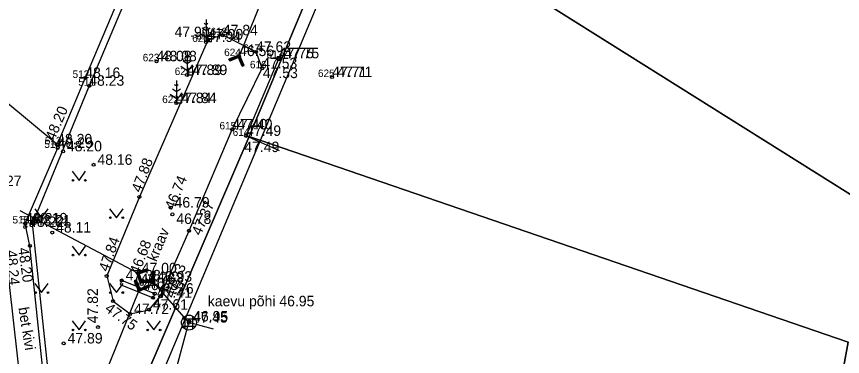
# Model space of a CAD drawing. Extents: x 640876 to 641418, y 6455595 to 6456085.
# Drawn here: x 641197.9 to 641253.1, y 6455921.6 to 6455944.3 of the extents above; entities that cross this region are included whole.
import ezdxf

# ---------------------------------------------------------------- set-up
doc = ezdxf.new("R2010")
doc.units = 0
for name, color, linetype in [('ABIJOONIS', 7, 'Continuous'), ('AED', 7, 'Continuous'), ('DKAEV', 7, 'Continuous'), ('DTRASS', 7, 'Continuous'), ('HALJASTUS', 7, 'Continuous'), ('KORGUS', 7, 'Continuous'), ('MOOTKORG', 7, 'Continuous'), ('MOOTKORG_MUU', 7, 'Continuous'), ('MOOTMPUNKT', 7, 'Continuous'), ('MOOTNR', 7, 'Continuous'), ('MOOTPIIR', 7, 'Continuous'), ('PIIR', 7, 'Continuous'), ('PUU', 7, 'Continuous'), ('SKTRASS', 7, 'Continuous'), ('TEE', 7, 'Continuous'), ('TRUUP', 7, 'Continuous'), ('VEEKOGU', 7, 'Continuous')]:
    doc.layers.add(name, color=color, linetype=linetype)

msp = doc.modelspace()

# ---------------------------------------------------------------- linework, layer by layer
at = {"layer": 'AED'}
for p, q in [((641215.287, 6455941.607), (641215.287, 6455941.357)), ((641215.287, 6455941.607), (641215.537, 6455941.607)), ((641215.537, 6455941.607), (641215.537, 6455941.357)), ((641215.287, 6455941.357), (641215.537, 6455941.357))]:
    msp.add_line(p, q, dxfattribs=at)
for points in [[(641160.606, 6455994.253), (641178.047, 6455995.168), (641191.652, 6455995.856), (641207.752, 6455996.687), (641222.341, 6455997.449), (641221.765, 6455994.718), (641219.959, 6455985.906), (641217.708, 6455975.561), (641214.2, 6455967.017), (641207.311, 6455950.541), (641202.719, 6455939.647), (641198.916, 6455930.446)], [(641215.412, 6455941.482), (641213.217, 6455936.294), (641215.427, 6455935.323)], [(641212.909, 6455897.356), (641213.691, 6455898.428), (641207.414, 6455903.573), (641201.239, 6455908.657), (641199.959, 6455920.79), (641198.916, 6455930.446)]]:
    msp.add_lwpolyline(points, dxfattribs=at)
at = {"layer": 'DKAEV'}
for p, q in [((641208.955, 6455924.063), (641209.821, 6455924.063)), ((641209.138, 6455923.38), (641209.138, 6455924.246)), ((641209.638, 6455924.246), (641209.638, 6455923.38)), ((641209.821, 6455923.563), (641208.955, 6455923.563))]:
    msp.add_line(p, q, dxfattribs=at)
msp.add_circle((641209.388, 6455923.813), 0.5, dxfattribs=at)
at = {"layer": 'DTRASS'}
for p, q in [((641206.935, 6455926.624), (641206.978, 6455927.258)), ((641206.964, 6455927.057), (641207.101, 6455926.976)), ((641206.966, 6455927.085), (641207.103, 6455927.004)), ((641206.968, 6455927.113), (641207.105, 6455927.032)), ((641206.97, 6455927.141), (641207.107, 6455927.06)), ((641206.972, 6455927.169), (641207.109, 6455927.088)), ((641206.974, 6455927.197), (641207.111, 6455927.116)), ((641206.976, 6455927.225), (641207.113, 6455927.144)), ((641206.978, 6455927.258), (641207.12, 6455927.249)), ((641206.978, 6455927.253), (641207.115, 6455927.172)), ((641207.001, 6455926.548), (641207.049, 6455927.253)), ((641207.022, 6455927.255), (641207.117, 6455927.199)), ((641207.067, 6455926.472), (641207.12, 6455927.249)), ((641207.078, 6455927.252), (641207.119, 6455927.227)), ((641205.851, 6455926.666), (641205.719, 6455926.611)), ((641205.719, 6455926.611), (641206.022, 6455925.894)), ((641205.746, 6455926.622), (641205.742, 6455926.557)), ((641205.772, 6455926.633), (641205.764, 6455926.506)), ((641205.798, 6455926.644), (641205.785, 6455926.455)), ((641205.785, 6455926.638), (641206.06, 6455925.987)), ((641205.824, 6455926.655), (641205.807, 6455926.403)), ((641205.85, 6455926.666), (641205.828, 6455926.352)), ((641205.871, 6455926.617), (641205.85, 6455926.301)), ((641205.851, 6455926.666), (641206.098, 6455926.08)), ((641205.893, 6455926.566), (641205.872, 6455926.25)), ((641205.915, 6455926.514), (641205.893, 6455926.199)), ((641206.3, 6455926.667), (641206.291, 6455926.525)), ((641206.291, 6455926.525), (641207.067, 6455926.472)), ((641206.293, 6455926.554), (641206.349, 6455926.521)), ((641206.295, 6455926.582), (641206.404, 6455926.517)), ((641206.296, 6455926.61), (641206.46, 6455926.513)), ((641206.296, 6455926.596), (641207.001, 6455926.548)), ((641206.298, 6455926.638), (641206.515, 6455926.51)), ((641206.3, 6455926.667), (641206.935, 6455926.624)), ((641206.3, 6455926.666), (641206.571, 6455926.506)), ((641206.354, 6455926.663), (641206.626, 6455926.502)), ((641206.409, 6455926.66), (641206.681, 6455926.498)), ((641206.465, 6455926.656), (641206.737, 6455926.495)), ((641206.52, 6455926.652), (641206.792, 6455926.491)), ((641206.575, 6455926.648), (641206.848, 6455926.487)), ((641206.631, 6455926.644), (641206.903, 6455926.483)), ((641206.686, 6455926.641), (641206.959, 6455926.48)), ((641206.742, 6455926.637), (641207.014, 6455926.476)), ((641206.797, 6455926.633), (641207.067, 6455926.473)), ((641206.853, 6455926.629), (641207.069, 6455926.501)), ((641206.908, 6455926.626), (641207.071, 6455926.529)), ((641206.936, 6455926.638), (641207.073, 6455926.557)), ((641206.938, 6455926.666), (641207.075, 6455926.585)), ((641206.94, 6455926.694), (641207.077, 6455926.613)), ((641206.941, 6455926.722), (641207.079, 6455926.641)), ((641206.943, 6455926.75), (641207.081, 6455926.669)), ((641206.945, 6455926.778), (641207.082, 6455926.697)), ((641206.947, 6455926.806), (641207.084, 6455926.725)), ((641206.949, 6455926.834), (641207.086, 6455926.753)), ((641206.951, 6455926.862), (641207.088, 6455926.781)), ((641206.953, 6455926.89), (641207.09, 6455926.808)), ((641206.955, 6455926.918), (641207.092, 6455926.836)), ((641206.957, 6455926.946), (641207.094, 6455926.864)), ((641206.959, 6455926.973), (641207.096, 6455926.892)), ((641206.96, 6455927.001), (641207.098, 6455926.92)), ((641206.962, 6455927.029), (641207.1, 6455926.948)), ((641209.388, 6455923.813), (641207.001, 6455926.548)), ((641198.97, 6455908.534), (641206.06, 6455925.987)), ((641205.936, 6455926.463), (641205.915, 6455926.148)), ((641205.958, 6455926.412), (641205.937, 6455926.096)), ((641205.979, 6455926.361), (641205.958, 6455926.045)), ((641206.001, 6455926.31), (641205.98, 6455925.994)), ((641206.023, 6455926.259), (641206.001, 6455925.943)), ((641206.022, 6455925.894), (641206.739, 6455926.196)), ((641206.044, 6455926.207), (641206.023, 6455925.894)), ((641206.066, 6455926.156), (641206.049, 6455925.905)), ((641206.06, 6455925.987), (641206.711, 6455926.262)), ((641206.087, 6455926.105), (641206.075, 6455925.916)), ((641206.098, 6455926.08), (641206.684, 6455926.328)), ((641206.111, 6455926.086), (641206.101, 6455925.927)), ((641206.137, 6455926.097), (641206.126, 6455925.938)), ((641206.163, 6455926.108), (641206.152, 6455925.949)), ((641206.189, 6455926.119), (641206.178, 6455925.96)), ((641206.214, 6455926.129), (641206.204, 6455925.97)), ((641206.24, 6455926.14), (641206.229, 6455925.981)), ((641206.266, 6455926.151), (641206.255, 6455925.992)), ((641206.292, 6455926.162), (641206.281, 6455926.003)), ((641206.318, 6455926.173), (641206.307, 6455926.014)), ((641206.343, 6455926.184), (641206.333, 6455926.025)), ((641206.369, 6455926.195), (641206.358, 6455926.036)), ((641206.395, 6455926.206), (641206.384, 6455926.047)), ((641206.421, 6455926.217), (641206.41, 6455926.058)), ((641206.446, 6455926.227), (641206.436, 6455926.068)), ((641206.472, 6455926.238), (641206.462, 6455926.079)), ((641206.498, 6455926.249), (641206.487, 6455926.09)), ((641206.524, 6455926.26), (641206.513, 6455926.101)), ((641206.55, 6455926.271), (641206.539, 6455926.112)), ((641206.575, 6455926.282), (641206.565, 6455926.123)), ((641206.601, 6455926.293), (641206.591, 6455926.134)), ((641206.627, 6455926.304), (641206.616, 6455926.145)), ((641206.653, 6455926.315), (641206.642, 6455926.156)), ((641206.679, 6455926.325), (641206.668, 6455926.166)), ((641206.684, 6455926.328), (641206.739, 6455926.196)), ((641206.701, 6455926.287), (641206.694, 6455926.177)), ((641206.723, 6455926.235), (641206.719, 6455926.188)), ((641206.913, 6455914.714), (641209.388, 6455923.813)), ((641211.031, 6455923.377), (641209.388, 6455923.813))]:
    msp.add_line(p, q, dxfattribs=at)
at = {"layer": 'HALJASTUS'}
for p, q in [((641201.571, 6455933.93), (641202.035, 6455933.324)), ((641202.035, 6455933.324), (641202.48, 6455933.93)), ((641199.071, 6455931.43), (641199.535, 6455930.824)), ((641199.535, 6455930.824), (641199.98, 6455931.43)), ((641204.071, 6455931.43), (641204.535, 6455930.824)), ((641204.535, 6455930.824), (641204.98, 6455931.43)), ((641201.571, 6455928.93), (641202.035, 6455928.324)), ((641202.035, 6455928.324), (641202.48, 6455928.93)), ((641199.071, 6455926.43), (641199.535, 6455925.824)), ((641199.535, 6455925.824), (641199.98, 6455926.43)), ((641204.071, 6455926.43), (641204.535, 6455925.824)), ((641204.535, 6455925.824), (641204.98, 6455926.43)), ((641201.571, 6455923.93), (641202.035, 6455923.324)), ((641202.035, 6455923.324), (641202.48, 6455923.93)), ((641206.571, 6455923.93), (641207.035, 6455923.324)), ((641207.035, 6455923.324), (641207.48, 6455923.93))]:
    msp.add_line(p, q, dxfattribs=at)
for centre in [(641201.634, 6455933.324), (641202.463, 6455933.324), (641199.134, 6455930.824), (641199.963, 6455930.824), (641204.134, 6455930.824), (641204.963, 6455930.824), (641201.634, 6455928.324), (641202.463, 6455928.324), (641199.134, 6455925.824), (641199.963, 6455925.824), (641204.134, 6455925.824), (641204.963, 6455925.824), (641201.634, 6455923.324), (641202.463, 6455923.324), (641206.634, 6455923.324), (641207.463, 6455923.324)]:
    msp.add_circle(centre, 0.055, dxfattribs=at)
at = {"layer": 'KORGUS'}
for centre in [(641210.68, 6455942.742), (641215.412, 6455941.482), (641207.223, 6455941.282), (641214.296, 6455940.813), (641209.264, 6455940.362), (641218.974, 6455940.229), (641208.551, 6455938.487), (641212.285, 6455936.73), (641213.217, 6455936.294), (641200.572, 6455935.729), (641203.009, 6455934.361), (641206.075, 6455932.221), (641208.286, 6455931.048), (641200.244, 6455929.836), (641209.398, 6455929.953), (641198.745, 6455928.944), (641203.888, 6455926.932), (641206.231, 6455926.396), (641207.472, 6455925.561), (641204.318, 6455925.253), (641203.299, 6455923.51), (641201.009, 6455922.421)]:
    msp.add_circle(centre, 0.1, dxfattribs=at)
at = {"layer": 'MOOTMPUNKT'}
for centre in [(641211.663, 6455943.019), (641210.535, 6455942.572), (641210.68, 6455942.742), (641213.882, 6455941.911), (641212.747, 6455941.628), (641215.412, 6455941.482), (641207.223, 6455941.282), (641214.296, 6455940.813), (641209.264, 6455940.362), (641218.974, 6455940.229), (641202.453, 6455940.169), (641202.719, 6455939.647), (641208.551, 6455938.487), (641212.285, 6455936.73), (641213.217, 6455936.294), (641200.572, 6455935.729), (641200.615, 6455935.492), (641200.968, 6455935.261), (641208.171, 6455931.503), (641198.434, 6455930.44), (641198.87, 6455930.305), (641198.916, 6455930.446), (641198.436, 6455930.206), (641205.972, 6455927.113), (641204.896, 6455926.636), (641205.895, 6455926.395), (641207.001, 6455926.548), (641206.06, 6455925.987), (641206.461, 6455926.112), (641206.986, 6455925.475), (641207.1, 6455925.748), (641205.458, 6455924.391), (641206.72, 6455924.676), (641209.388, 6455923.813), (641209.414, 6455923.892)]:
    msp.add_circle(centre, 0.1, dxfattribs=at)
at = {"layer": 'MOOTPIIR'}
msp.add_lwpolyline([(641060.916, 6455895.936), (641100.061, 6455950.482), (641099.586, 6455952.159), (641069.132, 6455984.035), (641066.132, 6455988.623), (641076.463, 6456005.049), (641230.642, 6456010.048), (641237.36, 6455995.24), (641237.24, 6455992.81), (641236.258, 6455990.888), (641229.041, 6455971.315), (641203.026, 6455909.57), (641225.257, 6455906.847), (641239.512, 6455898.491), (641200.195, 6455851.697), (641192.016, 6455859.099), (641169.785, 6455829.138), (641192.025, 6455807.568), (641252.96, 6455758.075), (641231.388, 6455736.74), (641191.474, 6455775.975), (641152.419, 6455787.914), (641136.351, 6455788.307), (641049.066, 6455856.043)], dxfattribs=at)
at = {"layer": 'PIIR'}
for points in [[(641222.58, 6455998.61), (641237.36, 6455995.24), (641235.34, 6455991.29), (641228.11, 6455971.68), (641220.5, 6455953.19), (641213.41, 6455936.25), (641201.58, 6455908.74), (641224.93, 6455905.88), (641191.87, 6455860.58), (641157.02, 6455885.66), (641160.91, 6455891.99), (641102.26, 6455951.82), (641074.95, 6455979.64), (641084.84, 6455991.92)], [(641280.77, 6455915.37), (641220.5, 6455953.19), (641228.11, 6455971.68), (641291.33, 6455932.26)], [(641270.69, 6455899.15), (641249.88, 6455902.84), (641253.51, 6455922.51), (641213.41, 6455936.25), (641220.5, 6455953.19), (641280.77, 6455915.37)], [(641201.58, 6455908.74), (641213.41, 6455936.25), (641253.51, 6455922.51), (641249.88, 6455902.84)]]:
    msp.add_lwpolyline(points, close=True, dxfattribs=at)
at = {"layer": 'PUU'}
for p, q in [((641210.535, 6455943.722), (641210.411, 6455943.805)), ((641210.535, 6455944.072), (641210.535, 6455942.572)), ((641210.66, 6455943.805), (641210.535, 6455943.722)), ((641210.111, 6455943.161), (641210.535, 6455942.878)), ((641210.535, 6455943.322), (641210.269, 6455943.5)), ((641210.802, 6455943.5), (641210.535, 6455943.322)), ((641210.535, 6455942.878), (641210.96, 6455943.161)), ((641210.895, 6455942.572), (641210.535, 6455942.572)), ((641209.264, 6455941.512), (641209.139, 6455941.595)), ((641209.264, 6455941.862), (641209.264, 6455940.362)), ((641209.388, 6455941.595), (641209.264, 6455941.512)), ((641208.839, 6455940.951), (641209.264, 6455940.668)), ((641209.264, 6455941.112), (641208.997, 6455941.289)), ((641209.53, 6455941.289), (641209.264, 6455941.112)), ((641209.264, 6455940.668), (641209.688, 6455940.951)), ((641209.624, 6455940.362), (641209.264, 6455940.362)), ((641208.551, 6455939.987), (641208.551, 6455938.487)), ((641208.551, 6455939.237), (641208.284, 6455939.414)), ((641208.551, 6455939.637), (641208.426, 6455939.719)), ((641208.675, 6455939.719), (641208.551, 6455939.637)), ((641208.817, 6455939.414), (641208.551, 6455939.237)), ((641208.127, 6455939.076), (641208.551, 6455938.793)), ((641208.551, 6455938.793), (641208.975, 6455939.076)), ((641208.911, 6455938.487), (641208.551, 6455938.487))]:
    msp.add_line(p, q, dxfattribs=at)
at = {"layer": 'SKTRASS'}
for p, q in [((641205.972, 6455927.113), (641198.106, 6455931.289)), ((641206.622, 6455927.401), (641205.882, 6455927.158)), ((641205.882, 6455927.158), (641206.125, 6455926.419)), ((641206.193, 6455927.111), (641205.883, 6455927.157)), ((641206.14, 6455927.093), (641205.891, 6455927.131)), ((641206.087, 6455927.076), (641205.9, 6455927.104)), ((641206.066, 6455927.054), (641205.909, 6455927.078)), ((641206.075, 6455927.027), (641205.917, 6455927.051)), ((641206.246, 6455927.128), (641205.933, 6455927.175)), ((641206.644, 6455927.334), (641205.972, 6455927.113)), ((641205.972, 6455927.113), (641206.193, 6455926.441)), ((641206.298, 6455927.145), (641205.986, 6455927.192)), ((641206.351, 6455927.163), (641206.038, 6455927.21)), ((641206.666, 6455927.266), (641206.062, 6455927.068)), ((641206.062, 6455927.068), (641206.26, 6455926.463)), ((641206.404, 6455927.18), (641206.091, 6455927.227)), ((641206.457, 6455927.197), (641206.144, 6455927.244)), ((641206.51, 6455927.215), (641206.197, 6455927.262)), ((641206.562, 6455927.232), (641206.249, 6455927.279)), ((641206.615, 6455927.249), (641206.302, 6455927.296)), ((641206.666, 6455927.267), (641206.355, 6455927.314)), ((641206.657, 6455927.294), (641206.408, 6455927.331)), ((641206.648, 6455927.32), (641206.461, 6455927.348)), ((641206.639, 6455927.347), (641206.513, 6455927.366)), ((641206.631, 6455927.373), (641206.566, 6455927.383)), ((641206.666, 6455927.266), (641206.622, 6455927.401)), ((641206.084, 6455927.001), (641205.926, 6455927.024)), ((641206.093, 6455926.974), (641205.935, 6455926.998)), ((641206.101, 6455926.947), (641205.944, 6455926.971)), ((641206.11, 6455926.921), (641205.952, 6455926.945)), ((641206.119, 6455926.894), (641205.961, 6455926.918)), ((641206.128, 6455926.868), (641205.97, 6455926.891)), ((641206.136, 6455926.841), (641205.979, 6455926.865)), ((641206.145, 6455926.814), (641205.987, 6455926.838)), ((641206.154, 6455926.788), (641205.996, 6455926.812)), ((641206.162, 6455926.761), (641206.005, 6455926.785)), ((641206.171, 6455926.735), (641206.014, 6455926.758)), ((641206.18, 6455926.708), (641206.022, 6455926.732)), ((641206.189, 6455926.681), (641206.031, 6455926.705)), ((641206.197, 6455926.655), (641206.04, 6455926.679)), ((641206.206, 6455926.628), (641206.049, 6455926.652)), ((641206.215, 6455926.602), (641206.057, 6455926.625)), ((641206.224, 6455926.575), (641206.066, 6455926.599)), ((641206.232, 6455926.549), (641206.075, 6455926.572)), ((641206.241, 6455926.522), (641206.084, 6455926.546)), ((641206.25, 6455926.495), (641206.092, 6455926.519)), ((641206.259, 6455926.469), (641206.101, 6455926.492)), ((641206.218, 6455926.45), (641206.11, 6455926.466)), ((641206.165, 6455926.432), (641206.118, 6455926.439)), ((641206.26, 6455926.463), (641206.125, 6455926.419))]:
    msp.add_line(p, q, dxfattribs=at)
at = {"layer": 'TEE'}
msp.add_line((641198.434, 6455930.44), (641200.615, 6455935.492), dxfattribs=at)
for points in [[(641219.562, 6455985.852), (641216.822, 6455976.794), (641214.309, 6455968.346), (641210.175, 6455958.541), (641206.979, 6455950.86), (641202.453, 6455940.169), (641200.572, 6455935.729), (641195.267, 6455940.101), (641183.381, 6455949.957), (641172.174, 6455959.233), (641160.995, 6455968.496)], [(641195.845, 6455932.936), (641197.091, 6455928.74), (641198.157, 6455919.205), (641198.959, 6455910.955), (641196.671, 6455908.21)], [(641227.727, 6455889.418), (641222.234, 6455890.597), (641218.433, 6455893.816), (641212.015, 6455899.131), (641206.417, 6455903.827), (641200.844, 6455908.419), (641200.675, 6455911.228), (641199.697, 6455919.825), (641198.745, 6455928.944), (641198.434, 6455930.44)]]:
    msp.add_lwpolyline(points, dxfattribs=at)
at = {"layer": 'TRUUP'}
for p, q in [((641212.784, 6455941.722), (641212.068, 6455941.417)), ((641212.124, 6455941.286), (641212.068, 6455941.417)), ((641212.085, 6455941.378), (641212.088, 6455941.425)), ((641212.747, 6455941.628), (641212.096, 6455941.351)), ((641212.107, 6455941.327), (641212.114, 6455941.436)), ((641212.709, 6455941.535), (641212.124, 6455941.286)), ((641212.129, 6455941.288), (641212.139, 6455941.447)), ((641212.155, 6455941.299), (641212.165, 6455941.458)), ((641212.181, 6455941.31), (641212.191, 6455941.469)), ((641212.207, 6455941.321), (641212.217, 6455941.48)), ((641212.232, 6455941.332), (641212.242, 6455941.491)), ((641212.258, 6455941.343), (641212.268, 6455941.502)), ((641212.284, 6455941.354), (641212.294, 6455941.513)), ((641212.31, 6455941.365), (641212.32, 6455941.524)), ((641212.335, 6455941.376), (641212.345, 6455941.535)), ((641212.361, 6455941.387), (641212.371, 6455941.546)), ((641212.387, 6455941.398), (641212.397, 6455941.557)), ((641212.413, 6455941.409), (641212.423, 6455941.568)), ((641212.438, 6455941.42), (641212.448, 6455941.579)), ((641212.464, 6455941.431), (641212.474, 6455941.59)), ((641212.49, 6455941.442), (641212.5, 6455941.601)), ((641212.516, 6455941.453), (641212.526, 6455941.612)), ((641212.541, 6455941.464), (641212.551, 6455941.623)), ((641212.567, 6455941.475), (641212.577, 6455941.634)), ((641212.593, 6455941.486), (641212.603, 6455941.645)), ((641212.619, 6455941.496), (641212.629, 6455941.656)), ((641212.644, 6455941.507), (641212.655, 6455941.667)), ((641212.67, 6455941.518), (641212.68, 6455941.678)), ((641212.696, 6455941.529), (641212.706, 6455941.689)), ((641212.958, 6455940.95), (641212.709, 6455941.535)), ((641212.72, 6455941.51), (641212.732, 6455941.699)), ((641212.741, 6455941.459), (641212.758, 6455941.71)), ((641213.024, 6455940.978), (641212.747, 6455941.628)), ((641212.763, 6455941.408), (641212.783, 6455941.721)), ((641213.089, 6455941.006), (641212.784, 6455941.722)), ((641212.785, 6455941.357), (641212.805, 6455941.673)), ((641212.807, 6455941.306), (641212.827, 6455941.622)), ((641212.829, 6455941.255), (641212.849, 6455941.571)), ((641212.85, 6455941.204), (641212.871, 6455941.519)), ((641212.872, 6455941.153), (641212.892, 6455941.468)), ((641212.894, 6455941.102), (641212.914, 6455941.417)), ((641212.916, 6455941.05), (641212.936, 6455941.366)), ((641212.938, 6455940.999), (641212.958, 6455941.315)), ((641212.958, 6455940.95), (641213.089, 6455941.006)), ((641212.959, 6455940.95), (641212.979, 6455941.264)), ((641212.985, 6455940.961), (641213.001, 6455941.213)), ((641213.011, 6455940.972), (641213.023, 6455941.162)), ((641213.037, 6455940.983), (641213.045, 6455941.111)), ((641213.062, 6455940.994), (641213.067, 6455941.06))]:
    msp.add_line(p, q, dxfattribs=at)
for points in [[(641215.125, 6455947.499), (641212.747, 6455941.628)], [(641204.896, 6455926.636), (641204.782, 6455926.363), (641206.986, 6455925.475), (641207.1, 6455925.748), (641204.896, 6455926.636)]]:
    msp.add_lwpolyline(points, dxfattribs=at)
at = {"layer": 'VEEKOGU'}
for points in [[(641209.77, 6455930.802), (641212.285, 6455936.73), (641214.296, 6455940.813), (641213.882, 6455941.911), (641211.663, 6455943.019), (641210.68, 6455942.742), (641206.075, 6455932.221)], [(641206.075, 6455932.221), (641203.888, 6455926.932), (641204.318, 6455925.253), (641205.458, 6455924.391), (641206.72, 6455924.676), (641207.472, 6455925.561), (641209.398, 6455929.953), (641209.77, 6455930.802)]]:
    msp.add_lwpolyline(points, dxfattribs=at)

# ---------------------------------------------------------------- texts
at = {"layer": 'ABIJOONIS'}
msp.add_text('kaevu põhi 46.95', height=0.7, dxfattribs=at).set_placement((641210.652, 6455924.904))
at = {"layer": 'DKAEV'}
msp.add_text('kaevu põhi 46.95', height=0.7, dxfattribs=at).set_placement((641210.652, 6455924.904))
at = {"layer": 'KORGUS'}
for s, p in [('47.90', (641208.429, 6455942.897)), ('48.08', (641207.573, 6455941.282)), ('47.75', (641215.762, 6455941.482)), ('47.89', (641209.614, 6455940.362)), ('47.53', (641214.335, 6455940.156)), ('47.71', (641219.324, 6455940.229)), ('47.84', (641208.901, 6455938.487)), ('47.40', (641212.635, 6455936.73)), ('47.49', (641213.095, 6455935.212)), (' 48.16', (641203.009, 6455934.361)), (' 48.11', (641200.244, 6455929.836)), (' 47.89', (641201.009, 6455922.421))]:
    msp.add_text(s, height=0.7, dxfattribs=at).set_placement(p)
for s, rotation, p in [('48.20', 66.6899, (641200.388, 6455935.937)), (' 47.88', 69.1723, (641206.075, 6455932.221)), (' 46.74', 67.3926, (641208.286, 6455931.048)), (' 47.37', 66.6924, (641210.078, 6455929.35)), (' 47.84', 70.0885, (641203.888, 6455926.932)), (' 46.68', 68.5544, (641205.947, 6455926.737)), (' 48.20', 278.0679, (641197.922, 6455929.042)), (' 48.24', 274.847, (641197.151, 6455928.887)), (' 47.33', 69.2743, (641208.287, 6455925.163)), (' 47.82', 90, (641203.299, 6455923.51)), (' 47.75', 323.9814, (641203.503, 6455924.779))]:
    msp.add_text(s, height=0.7, rotation=rotation, dxfattribs=at).set_placement(p)
at = {"layer": 'MOOTKORG'}
for s, p in [('47.84', (641211.663, 6455943.019)), ('47.94', (641210.535, 6455942.572)), ('47.90', (641210.68, 6455942.742)), ('47.62', (641213.882, 6455941.911)), ('48.08', (641207.223, 6455941.282)), ('46.56', (641212.747, 6455941.628)), ('47.75', (641215.412, 6455941.482)), ('47.53', (641214.296, 6455940.813)), ('48.16', (641202.453, 6455940.169)), ('47.89', (641209.264, 6455940.362)), ('47.71', (641218.974, 6455940.229)), ('48.23', (641202.719, 6455939.647)), ('47.84', (641208.551, 6455938.487)), ('47.40', (641212.285, 6455936.73)), ('47.49', (641213.217, 6455936.294)), ('48.20', (641200.572, 6455935.729)), ('48.29', (641200.615, 6455935.492)), (' 48.20', (641200.968, 6455935.261)), ('48.27', (641195.845, 6455932.936)), (' 46.79', (641208.171, 6455931.503)), ('48.21', (641198.434, 6455930.44)), (' 48.22', (641198.436, 6455930.206)), ('48.19', (641198.916, 6455930.446)), (' 48.21', (641198.87, 6455930.305)), (' 46.78', (641208.286, 6455930.411)), (' 47.00', (641205.972, 6455927.113)), (' 47.38', (641204.896, 6455926.636)), (' 46.76', (641205.895, 6455926.395)), (' 46.93', (641207.001, 6455926.548)), (' 46.53', (641206.06, 6455925.987)), (' 46.78', (641206.461, 6455926.112)), (' 47.41', (641206.986, 6455925.475)), (' 47.26', (641207.1, 6455925.748)), (' 47.72', (641205.458, 6455924.391)), (' 47.61', (641206.72, 6455924.676))]:
    msp.add_text(s, height=0.7, dxfattribs=at).set_placement(p)
at = {"layer": 'MOOTKORG_MUU'}
for s, p in [(' 47.45', (641209.388, 6455923.813)), (' 46.95', (641209.414, 6455923.892))]:
    msp.add_text(s, height=0.7, dxfattribs=at).set_placement(p)
at = {"layer": 'MOOTNR'}
for s, p in [('620', (641209.61, 6455942.572)), ('619', (641209.855, 6455942.742)), ('618', (641210.838, 6455943.019)), ('624', (641211.747, 6455941.628)), ('617', (641213.032, 6455941.911)), ('613', (641214.587, 6455941.482)), ('623', (641206.298, 6455941.282)), ('621', (641208.439, 6455940.362)), ('616', (641213.471, 6455940.813)), ('512', (641201.603, 6455940.169)), ('625', (641218.024, 6455940.229)), ('511', (641201.994, 6455939.647)), ('622', (641207.601, 6455938.487)), ('615', (641211.435, 6455936.73)), ('614', (641212.317, 6455936.294)), ('514', (641199.715, 6455935.492)), ('513', (641199.747, 6455935.729)), ('515', (641197.584, 6455930.44)), ('516', (641198.091, 6455930.446))]:
    msp.add_text(s, height=0.5, dxfattribs=at).set_placement(p)
at = {"layer": 'TEE'}
msp.add_text('bet kivi', height=0.7, rotation=279.2135, dxfattribs=at).set_placement((641197.973, 6455924.797))
at = {"layer": 'VEEKOGU'}
msp.add_text('kraav', height=0.7, rotation=67.3204, dxfattribs=at).set_placement((641207.211, 6455927.843))

doc.saveas('drawing.dxf')
